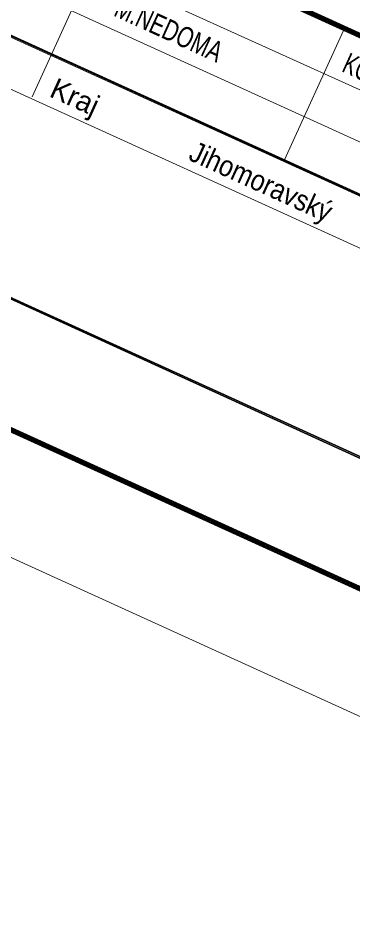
# Model space of a CAD drawing. Extents: x -597411 to -596783, y -1159250 to -1158536.
# Drawn here: x -597224.7 to -597144.1, y -1159250.4 to -1159030.7 of the extents above; entities that cross this region are included whole.
import ezdxf

# ---------------------------------------------------------------- set-up
doc = ezdxf.new("R2010")
doc.units = 0
doc.header["$LTSCALE"] = 2
doc.layers.add('1', color=7, linetype='Continuous', lineweight=13)
doc.layers.add('62', color=7, linetype='Continuous', lineweight=13)

msp = doc.modelspace()

# ---------------------------------------------------------------- linework, layer by layer
at = {"layer": '1'}
for p, q in [((-597319.261, -1158967.378), (-597095.014, -1159069.516)), ((-597323.983, -1158977.76), (-597099.731, -1159079.88)), ((-597328.902, -1158988.575), (-597013.077, -1159132.405)), ((-597328.838, -1158988.429), (-597013.013, -1159132.259)), ((-597328.768, -1158988.288), (-597012.949, -1159132.124)), ((-597328.704, -1158988.142), (-597012.88, -1159131.972)), ((-597333.641, -1158998.941), (-597017.793, -1159142.792)), ((-597202.423, -1159008.074), (-597221.312, -1159049.579)), ((-597146.352, -1159033.604), (-597160.53, -1159064.727)), ((-597352.588, -1159040.596), (-597036.769, -1159184.422)), ((-597352.524, -1159040.45), (-597036.705, -1159184.276)), ((-597352.721, -1159040.883), (-597036.902, -1159184.709)), ((-597352.657, -1159040.737), (-597036.838, -1159184.574))]:
    msp.add_line(p, q, dxfattribs=at)
for points in [[(-597315.087, -1158955.531), (-597365.819, -1159066.909), (-597047.945, -1159211.688), (-596997.226, -1159100.289)], [(-597315.01, -1158955.747), (-597365.608, -1159066.838), (-597048.033, -1159211.473), (-596997.425, -1159100.37)], [(-597314.934, -1158955.952), (-597365.399, -1159066.755), (-597048.104, -1159211.262), (-596997.634, -1159100.453)], [(-597314.851, -1158956.173), (-597365.189, -1159066.673), (-597048.181, -1159211.047), (-596997.85, -1159100.53)], [(-597314.78, -1158956.383), (-597364.979, -1159066.591), (-597048.258, -1159210.842), (-596998.066, -1159100.607)], [(-597314.692, -1158956.587), (-597364.768, -1159066.52), (-597048.346, -1159210.627), (-596998.271, -1159100.683)], [(-597314.62, -1158956.809), (-597364.552, -1159066.442), (-597048.423, -1159210.411), (-596998.487, -1159100.76)], [(-597314.538, -1158957.019), (-597364.343, -1159066.36), (-597048.5, -1159210.207), (-596998.691, -1159100.837)]]:
    msp.add_lwpolyline(points, close=True, dxfattribs=at)
at = {"layer": '62'}
msp.add_lwpolyline([(-597165.078, -1158535.742), (-596782.855, -1158709.829), (-597029.064, -1159250.4), (-597411.286, -1159076.313)], close=True, dxfattribs=at)

# ---------------------------------------------------------------- texts
at = {"layer": '1'}
for s, rotation, width, p in [('M.NEDOMA', 335.481, 0.75, (-597201.949, -1159029.98)), ('KONTROLOVAL', 335.514, 0.7, (-597147.008, -1159043.379)), ('Jihomoravský', 335.514, 0.9, (-597183.945, -1159064.657))]:
    msp.add_text(s, height=5, rotation=rotation, dxfattribs=dict(at, width=width)).set_placement(p)
msp.add_text('Kraj', height=5, rotation=335.514, dxfattribs=at).set_placement((-597217.444, -1159049.405))

doc.saveas('drawing.dxf')
